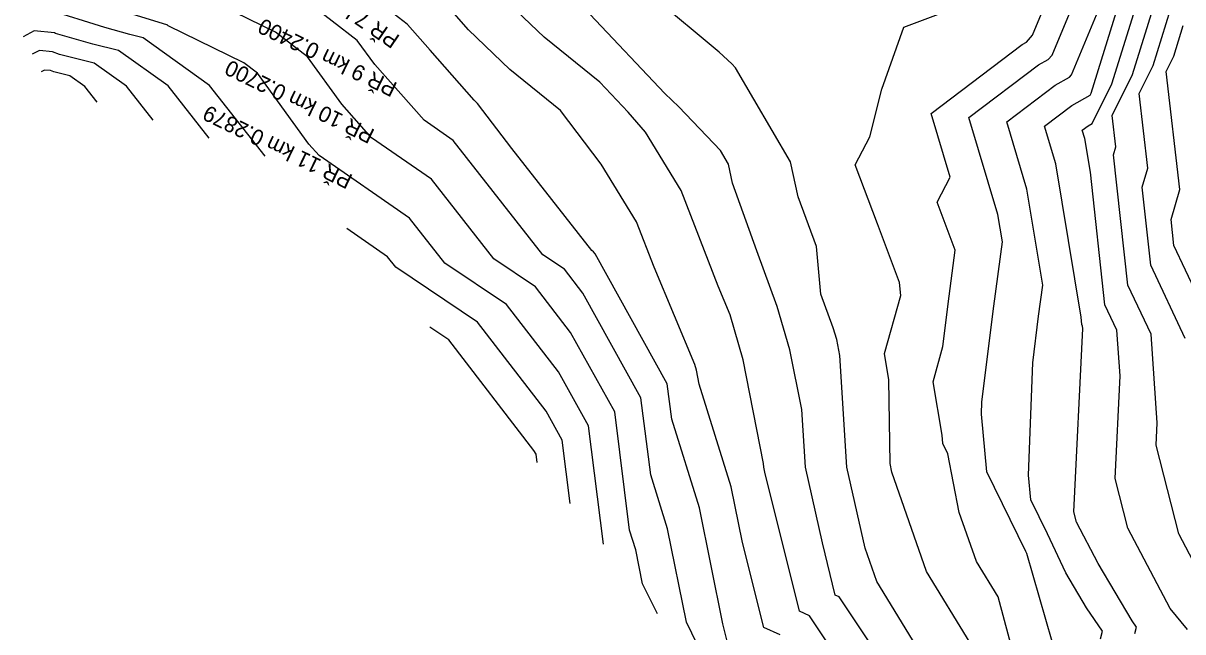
# Model space of a CAD drawing. Extents: x -549394 to -546608, y -1037055 to -1033629.
# Drawn here: x -548873 to -548203, y -1034976 to -1034624 of the extents above; entities that cross this region are included whole.
import ezdxf

# ---------------------------------------------------------------- set-up
doc = ezdxf.new("R2010")
doc.units = 0
for name, color, linetype in [('hlavni_vrst', 7, 'Continuous'), ('norm_vrst', 7, 'Continuous'), ('x_popis_pricne_rezy_C123', 7, 'Continuous')]:
    doc.layers.add(name, color=color, linetype=linetype)

msp = doc.modelspace()

# ---------------------------------------------------------------- linework, layer by layer
at = {"layer": 'hlavni_vrst'}
for p, q in [((-548651.16, -1034624.47), (-548690.63, -1034593.97)), ((-548243.89, -1034659.08), (-548224.81, -1034597.75)), ((-548364.17, -1034626.36), (-548320.4, -1034609.68)), ((-548866.72, -1034628.38), (-548873.13, -1034631.84)), ((-548855.13, -1034629.59), (-548866.72, -1034628.38)), ((-548650.96, -1034624.74), (-548651.16, -1034624.47)), ((-548637.84, -1034639.57), (-548650.96, -1034624.74)), ((-548376.8, -1034662.17), (-548364.17, -1034626.36)), ((-548854.38, -1034629.9), (-548855.13, -1034629.59)), ((-548832.92, -1034636.04), (-548854.38, -1034629.9)), ((-548817.95, -1034639.72), (-548832.92, -1034636.04)), ((-548789.41, -1034660.11), (-548817.95, -1034639.72)), ((-548612.48, -1034668.53), (-548637.84, -1034639.57)), ((-548765.69, -1034690.43), (-548789.41, -1034660.11)), ((-548383.78, -1034689.57), (-548376.8, -1034662.17)), ((-548255.14, -1034681.89), (-548243.89, -1034659.08)), ((-548611.56, -1034669.41), (-548612.48, -1034668.53)), ((-548610.44, -1034670.32), (-548611.56, -1034669.41)), ((-548590.69, -1034696.28), (-548610.44, -1034670.32)), ((-548257.48, -1034683.19), (-548255.14, -1034681.89)), ((-548260.92, -1034685.79), (-548257.48, -1034683.19)), ((-548259.49, -1034690.57), (-548260.92, -1034685.79)), ((-548392.2, -1034705.88), (-548383.78, -1034689.57)), ((-548256.29, -1034709.94), (-548259.49, -1034690.57)), ((-548544.5, -1034755.28), (-548590.69, -1034696.28)), ((-548379.35, -1034739.81), (-548392.2, -1034705.88)), ((-548247.86, -1034786.65), (-548256.29, -1034709.94)), ((-548366.57, -1034773.82), (-548379.35, -1034739.81)), ((-548543.46, -1034755.98), (-548544.5, -1034755.28)), ((-548542.59, -1034757.11), (-548543.46, -1034755.98)), ((-548500.86, -1034832.22), (-548542.59, -1034757.11)), ((-548365.91, -1034781.32), (-548366.57, -1034773.82)), ((-548375.22, -1034814.79), (-548365.91, -1034781.32)), ((-548240.98, -1034801.29), (-548247.86, -1034786.65)), ((-548627.19, -1034806.84), (-548638.03, -1034799.56)), ((-548239.11, -1034827.58), (-548240.98, -1034801.29)), ((-548577.92, -1034870.73), (-548627.19, -1034806.84)), ((-548372.7, -1034829.89), (-548375.22, -1034814.79)), ((-548372.03, -1034878.25), (-548372.7, -1034829.89)), ((-548241.98, -1034887.04), (-548239.11, -1034827.58)), ((-548498.28, -1034852.77), (-548500.86, -1034832.22)), ((-548482.21, -1034903.88), (-548498.28, -1034852.77)), ((-548576.7, -1034872.92), (-548577.92, -1034870.73)), ((-548576.1, -1034877.68), (-548576.7, -1034872.92)), ((-548371.03, -1034883.34), (-548372.03, -1034878.25)), ((-548350.92, -1034940.67), (-548371.03, -1034883.34)), ((-548234.71, -1034915.58), (-548241.98, -1034887.04)), ((-548468.66, -1034970.86), (-548482.21, -1034903.88)), ((-548210.1, -1034962.11), (-548234.71, -1034915.58)), ((-548325.66, -1034981.81), (-548350.92, -1034940.67)), ((-548200.15, -1034974.14), (-548210.1, -1034962.11)), ((-548465.78, -1034982.48), (-548468.66, -1034970.86))]:
    msp.add_line(p, q, dxfattribs=at)
at = {"layer": 'norm_vrst'}
for p, q in [((-548278.43, -1034642.39), (-548251.62, -1034577.85)), ((-548571.95, -1034632.13), (-548618.9, -1034587.2)), ((-548255.83, -1034664.46), (-548232.22, -1034588.56)), ((-548470.77, -1034640.66), (-548527.77, -1034593.3)), ((-548289.72, -1034630.93), (-548274.82, -1034595.07)), ((-548790.03, -1034624.96), (-548864.76, -1034601.89)), ((-548615.69, -1034627.87), (-548637.45, -1034603.02)), ((-548231.95, -1034653.7), (-548217.4, -1034606.94)), ((-548727.25, -1034629.19), (-548758.49, -1034613.9)), ((-548680.02, -1034633.92), (-548708.94, -1034611.58)), ((-548267.15, -1034653.85), (-548249.83, -1034612.15)), ((-548825.89, -1034626.38), (-548859.33, -1034616.05)), ((-548502.34, -1034664.67), (-548545.52, -1034618.83)), ((-548220.01, -1034648.33), (-548209.99, -1034616.13)), ((-548811.4, -1034630.52), (-548825.89, -1034626.38)), ((-548789.89, -1034625.01), (-548790.03, -1034624.96)), ((-548789.81, -1034625.02), (-548789.89, -1034625.01)), ((-548789.26, -1034625.42), (-548789.81, -1034625.02)), ((-548745.56, -1034646.8), (-548789.26, -1034625.42)), ((-548591.75, -1034650.77), (-548615.69, -1034627.87)), ((-548208.07, -1034642.95), (-548202.58, -1034625.32)), ((-548803.88, -1034632.37), (-548811.4, -1034630.52)), ((-548765.36, -1034659.89), (-548803.88, -1034632.37)), ((-548708.89, -1034643.38), (-548727.25, -1034629.19)), ((-548669.95, -1034647.77), (-548680.02, -1034633.92)), ((-548539.89, -1034658.03), (-548571.95, -1034632.13)), ((-548295.78, -1034636.32), (-548293.11, -1034634.84)), ((-548293.11, -1034634.84), (-548289.72, -1034630.93)), ((-548863.74, -1034639.7), (-548867.91, -1034641.95)), ((-548856.21, -1034640.48), (-548863.74, -1034639.7)), ((-548852.23, -1034642.1), (-548856.21, -1034640.48)), ((-548832.03, -1034647.07), (-548852.23, -1034642.1)), ((-548463.54, -1034647.47), (-548470.77, -1034640.66)), ((-548348.38, -1034676.06), (-548295.78, -1034636.32)), ((-548813.47, -1034660.33), (-548832.03, -1034647.07)), ((-548737.75, -1034652.83), (-548745.56, -1034646.8)), ((-548688.95, -1034670.79), (-548708.89, -1034643.38)), ((-548641.45, -1034679.99), (-548669.95, -1034647.77)), ((-548461.34, -1034649.76), (-548463.54, -1034647.47)), ((-548326.51, -1034678.49), (-548286.2, -1034648.04)), ((-548286.2, -1034648.04), (-548280.68, -1034644.97)), ((-548280.68, -1034644.97), (-548278.43, -1034642.39)), ((-548228.02, -1034664.57), (-548220.01, -1034648.33)), ((-548212.46, -1034651.84), (-548208.07, -1034642.95)), ((-548860.76, -1034651.01), (-548862.69, -1034652.05)), ((-548857.28, -1034651.37), (-548860.76, -1034651.01)), ((-548855.44, -1034652.12), (-548857.28, -1034651.37)), ((-548846.1, -1034654.42), (-548855.44, -1034652.12)), ((-548837.52, -1034660.55), (-548846.1, -1034654.42)), ((-548707.94, -1034693.82), (-548737.75, -1034652.83)), ((-548562.6, -1034674.33), (-548591.75, -1034650.77)), ((-548429.57, -1034704.15), (-548461.34, -1034649.76)), ((-548276.63, -1034659.75), (-548268.24, -1034655.11)), ((-548268.24, -1034655.11), (-548267.15, -1034653.85)), ((-548243.59, -1034677.3), (-548231.95, -1034653.7)), ((-548204.47, -1034720.05), (-548212.46, -1034651.84)), ((-548830.38, -1034669.67), (-548837.52, -1034660.55)), ((-548798.04, -1034680.05), (-548813.47, -1034660.33)), ((-548733.35, -1034700.81), (-548765.36, -1034659.89)), ((-548523.51, -1034675.41), (-548539.89, -1034658.03)), ((-548304.65, -1034680.92), (-548276.63, -1034659.75)), ((-548494.24, -1034672.3), (-548502.34, -1034664.67)), ((-548267.05, -1034671.47), (-548256.37, -1034665.55)), ((-548256.37, -1034665.55), (-548255.83, -1034664.46)), ((-548222.97, -1034707.7), (-548228.02, -1034664.57)), ((-548671.75, -1034690.23), (-548688.95, -1034670.79)), ((-548538.97, -1034705.38), (-548562.6, -1034674.33)), ((-548513.49, -1034686.98), (-548523.51, -1034675.41)), ((-548470.06, -1034697.47), (-548494.24, -1034672.3)), ((-548282.79, -1034683.36), (-548267.05, -1034671.47)), ((-548624.5, -1034691.68), (-548641.45, -1034679.99)), ((-548337.32, -1034712.91), (-548348.38, -1034676.06)), ((-548309.7, -1034734.52), (-548326.51, -1034678.49)), ((-548292.97, -1034719.87), (-548304.65, -1034680.92)), ((-548241.48, -1034695.36), (-548243.59, -1034677.3)), ((-548492.87, -1034720.57), (-548513.49, -1034686.98)), ((-548276.23, -1034705.22), (-548282.79, -1034683.36)), ((-548702.06, -1034700.47), (-548707.94, -1034693.82)), ((-548637.15, -1034714.09), (-548671.75, -1034690.23)), ((-548572.82, -1034757.69), (-548624.5, -1034691.68)), ((-548242.85, -1034699.92), (-548241.48, -1034695.36)), ((-548649.81, -1034736.5), (-548702.06, -1034700.47)), ((-548465.44, -1034705.37), (-548470.06, -1034697.47)), ((-548234.57, -1034775.21), (-548242.85, -1034699.92)), ((-548518.57, -1034738.63), (-548538.97, -1034705.38)), ((-548463.08, -1034716.32), (-548465.44, -1034705.37)), ((-548425.23, -1034724.31), (-548429.57, -1034704.15)), ((-548261.63, -1034793.74), (-548276.23, -1034705.22)), ((-548226.24, -1034718.6), (-548222.97, -1034707.7)), ((-548601.13, -1034760.1), (-548637.15, -1034714.09)), ((-548344.83, -1034727.44), (-548337.32, -1034712.91)), ((-548471.49, -1034775.81), (-548492.87, -1034720.57)), ((-548449.09, -1034755.53), (-548463.08, -1034716.32)), ((-548283.82, -1034775.31), (-548292.97, -1034719.87)), ((-548221.28, -1034763.77), (-548226.24, -1034718.6)), ((-548209.64, -1034737.28), (-548204.47, -1034720.05)), ((-548414.49, -1034752.87), (-548425.23, -1034724.31)), ((-548334.33, -1034755.14), (-548344.83, -1034727.44)), ((-548307.09, -1034750.36), (-548309.7, -1034734.52)), ((-548662.46, -1034758.92), (-548686.09, -1034742.62)), ((-548629.45, -1034762.51), (-548649.81, -1034736.5)), ((-548508.38, -1034764.95), (-548518.57, -1034738.63)), ((-548207.99, -1034752.34), (-548209.64, -1034737.28)), ((-548437.23, -1034787.55), (-548449.09, -1034755.53)), ((-548412.05, -1034780.52), (-548414.49, -1034752.87)), ((-548337.87, -1034781.62), (-548334.33, -1034755.14)), ((-548312.05, -1034787.45), (-548307.09, -1034750.36)), ((-548181.64, -1034808.42), (-548207.99, -1034752.34)), ((-548657.77, -1034764.92), (-548662.46, -1034758.92)), ((-548593.7, -1034786.49), (-548629.45, -1034762.51)), ((-548576.95, -1034776.32), (-548601.13, -1034760.1)), ((-548560.2, -1034766.15), (-548572.82, -1034757.69)), ((-548610.44, -1034796.66), (-548657.77, -1034764.92)), ((-548549.65, -1034779.83), (-548560.2, -1034766.15)), ((-548484.96, -1034821.2), (-548508.38, -1034764.95)), ((-548201.42, -1034806.04), (-548221.28, -1034763.77)), ((-548464.57, -1034792.45), (-548471.49, -1034775.81)), ((-548286.22, -1034793.29), (-548283.82, -1034775.31)), ((-548221.2, -1034803.67), (-548234.57, -1034775.21)), ((-548556.72, -1034802.56), (-548576.95, -1034776.32)), ((-548516.03, -1034840.36), (-548549.65, -1034779.83)), ((-548404.86, -1034799.92), (-548412.05, -1034780.52)), ((-548341.52, -1034810.82), (-548337.87, -1034781.62)), ((-548563.79, -1034825.28), (-548593.7, -1034786.49)), ((-548429.94, -1034812.59), (-548437.23, -1034787.55)), ((-548318.96, -1034842.78), (-548312.05, -1034787.45)), ((-548456.99, -1034818.49), (-548464.57, -1034792.45)), ((-548289.58, -1034820.09), (-548286.22, -1034793.29)), ((-548261.15, -1034798.08), (-548261.63, -1034793.74)), ((-548570.85, -1034848.01), (-548610.44, -1034796.66)), ((-548531.2, -1034848.5), (-548556.72, -1034802.56)), ((-548402.9, -1034806.68), (-548404.86, -1034799.92)), ((-548265.76, -1034906.31), (-548260.66, -1034800.4)), ((-548260.76, -1034798.91), (-548261.15, -1034798.08)), ((-548260.66, -1034800.4), (-548260.76, -1034798.91)), ((-548401.05, -1034816.01), (-548402.9, -1034806.68)), ((-548217.57, -1034854.76), (-548221.2, -1034803.67)), ((-548423.1, -1034847.13), (-548429.94, -1034812.59)), ((-548396.99, -1034880.35), (-548401.05, -1034816.01)), ((-548347.17, -1034831.13), (-548341.52, -1034810.82)), ((-548484.03, -1034824.39), (-548484.96, -1034821.2)), ((-548445.15, -1034878.24), (-548456.99, -1034818.49)), ((-548292.05, -1034885.13), (-548289.58, -1034820.09)), ((-548546.37, -1034856.64), (-548563.79, -1034825.28)), ((-548482.44, -1034832.44), (-548484.03, -1034824.39)), ((-548463.81, -1034891.72), (-548482.44, -1034832.44)), ((-548342.03, -1034861.93), (-548347.17, -1034831.13)), ((-548510.43, -1034884.81), (-548516.03, -1034840.36)), ((-548319.23, -1034849.75), (-548318.96, -1034842.78)), ((-548561.54, -1034864.78), (-548570.85, -1034848.01)), ((-548522.59, -1034916.85), (-548531.2, -1034848.5)), ((-548421, -1034880.38), (-548423.1, -1034847.13)), ((-548316.17, -1034883.06), (-548319.23, -1034849.75)), ((-548537.76, -1034924.95), (-548546.37, -1034856.64)), ((-548218.2, -1034867.77), (-548217.57, -1034854.76)), ((-548341.58, -1034866.81), (-548342.03, -1034861.93)), ((-548556.93, -1034901.32), (-548561.54, -1034864.78)), ((-548338.72, -1034872.64), (-548341.58, -1034866.81)), ((-548205.16, -1034918.95), (-548218.2, -1034867.77)), ((-548332.02, -1034906.58), (-548338.72, -1034872.64)), ((-548445.01, -1034880.42), (-548445.15, -1034878.24)), ((-548444.37, -1034883.28), (-548445.01, -1034880.42)), ((-548424.4, -1034963.7), (-548444.37, -1034883.28)), ((-548411.2, -1034924.15), (-548421, -1034880.38)), ((-548386.51, -1034927.14), (-548396.99, -1034880.35)), ((-548293.55, -1034929.15), (-548316.17, -1034883.06)), ((-548500.62, -1034916.03), (-548510.43, -1034884.81)), ((-548290.75, -1034899.3), (-548292.05, -1034885.13)), ((-548457.28, -1034924), (-548463.81, -1034891.72)), ((-548281.13, -1034918.9), (-548290.75, -1034899.3)), ((-548322.07, -1034934.95), (-548332.02, -1034906.58)), ((-548264.26, -1034912.2), (-548265.76, -1034906.31)), ((-548519.03, -1034928.18), (-548522.59, -1034916.85)), ((-548489.69, -1034970.04), (-548500.62, -1034916.03)), ((-548251.67, -1034936.01), (-548264.26, -1034912.2)), ((-548270.4, -1034941.39), (-548281.13, -1034918.9)), ((-548190.85, -1034946.02), (-548205.16, -1034918.95)), ((-548515.06, -1034947.79), (-548519.03, -1034928.18)), ((-548445.09, -1034973.09), (-548457.28, -1034924)), ((-548403.71, -1034954.3), (-548411.2, -1034924.15)), ((-548379.76, -1034946.38), (-548386.51, -1034927.14)), ((-548292.99, -1034930.32), (-548293.55, -1034929.15)), ((-548278.35, -1034981.13), (-548292.99, -1034930.32)), ((-548309.57, -1034955.32), (-548322.07, -1034934.95)), ((-548232.06, -1034969.21), (-548251.67, -1034936.01)), ((-548258.44, -1034961.64), (-548270.4, -1034941.39)), ((-548506.52, -1034965.19), (-548515.06, -1034947.79)), ((-548341.75, -1035008.31), (-548379.76, -1034946.38)), ((-548401.52, -1034955.28), (-548403.71, -1034954.3)), ((-548367.9, -1035005.68), (-548401.52, -1034955.28)), ((-548297.51, -1035000.24), (-548309.57, -1034955.32)), ((-548418.56, -1034966.31), (-548424.4, -1034963.7)), ((-548249.2, -1034975.11), (-548258.44, -1034961.64)), ((-548480.23, -1034989.31), (-548489.69, -1034970.04)), ((-548394.04, -1035003.04), (-548418.56, -1034966.31)), ((-548229.52, -1034972.92), (-548232.06, -1034969.21)), ((-548435.59, -1034977.33), (-548445.09, -1034973.09)), ((-548250.47, -1034979.54), (-548249.2, -1034975.11)), ((-548230.55, -1034976.55), (-548229.52, -1034972.92))]:
    msp.add_line(p, q, dxfattribs=at)

# ---------------------------------------------------------------- texts
at = {"layer": 'x_popis_pricne_rezy_C123'}
for s, rotation, p in [('PŘ 7 km 0.1800', 145.54539, (-548654.83, -1034631.61)), ('PŘ 9 km 0.2400', 154.11426, (-548656.24, -1034658.77)), ('PŘ 10 km 0.2700', 154.11426, (-548669.34, -1034685.76)), ('PŘ 11 km 0.2879', 154.11426, (-548682.04, -1034711.93))]:
    msp.add_text(s, height=9.0627, rotation=rotation, dxfattribs=at).set_placement(p)

doc.saveas('drawing.dxf')
